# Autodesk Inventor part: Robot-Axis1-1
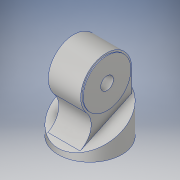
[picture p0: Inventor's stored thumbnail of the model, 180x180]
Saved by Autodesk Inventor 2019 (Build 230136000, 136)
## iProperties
Created: 2018-07
Part Number: Robot-Axis1-1
Material: Aluminum 6061
Description: 123456
Document SubType Name: Modeling
Designer: Power User
Mass: 5063.94 g
Surface Area: 1124.06 cm^2
Volume: 1875.53 cm^3
Density: 2.7 g/cm^3
Appearance: Aluminum - Flat
Title: GEAR
Author: Power User
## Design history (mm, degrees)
sketch "Sketch6"
  geometry: C1 r 75 at (0, 0); 1 further point
  constraints: 1 centre point, 1 coincident
  dimensions: "d44" = 150 diameter of C1
extrude "Extrusion5" new body sketch "Sketch6" distance "d45" = 100; taper "d46" = 0 deg
sketch "Sketch7"
  geometry: L1 (0, 75)-(0, -75) reference; L2 (0, 102.879)-(99.808, -111.161); L3 (0, 75)-(100, 75) reference; L4 (0, 102.879)-(-29.654, 102.879); L5 (-29.654, 102.879)-(-29.654, -111.161); L6 (-29.654, -111.161)-(99.808, -111.161); 2 further points
  constraints: 8 end point, 3 point on line, 2 perpendicular, 1 horizontal
  dimensions: "d47" = 25 deg angle of L1 L2; "d49" = 13 distance from line of L1 point (13, 75)
extrude "Extrusion6" sketch "Sketch7" stored distance "d50" = 200; taper "d51" = 0 deg
sketch "Sketch8"
  geometry: L1 (82.946, -75)-(13, 75) reference; L2 (128, -60)-(75.952, -60); L3 (13, 75)-(82.946, -75) reference; L4 (82.946, -75)-(0, -75) reference; L5 (0, -75)-(0, 75) reference; L6 (0, 75)-(13, 75) reference; L7 (0, 75)-(0, -75) reference; L8 (19.444, 61.181)-(75.952, -60); C1 r 56 at (128, 0); C2 r 15 at (128, 0); A1 r 60 centre (128, 0) between (128, -60) and (89.273, 45.828); A2 r 45 centre (60.228, 80.199) between (19.444, 61.181) and (89.273, 45.828); 1 further point
  constraints: 4 centre point, 4 end point, 4 point on circle, 3 tangent, 2 coincident, 2 point on line, 1 collinear, 1 horizontal
  dimensions: "d52" = 75 distance from line of L4 C1.centre; "d53" = 120 diameter of A1; "d54" = 112 diameter of C1; "d55" = 128 distance from line of C1.centre L7; "d56" = 45 radius of A2; "d57" = 30 diameter of C2
  node "Project Cut Edges2"
extrude "Extrusion7" join sketch "Sketch8" stored distance "d58" = 76; taper "d59" = 0 deg
extrude "Extrusion8" join sketch "Sketch8" stored distance "d60" = 80; taper "d61" = 0 deg
body "Solid2"
